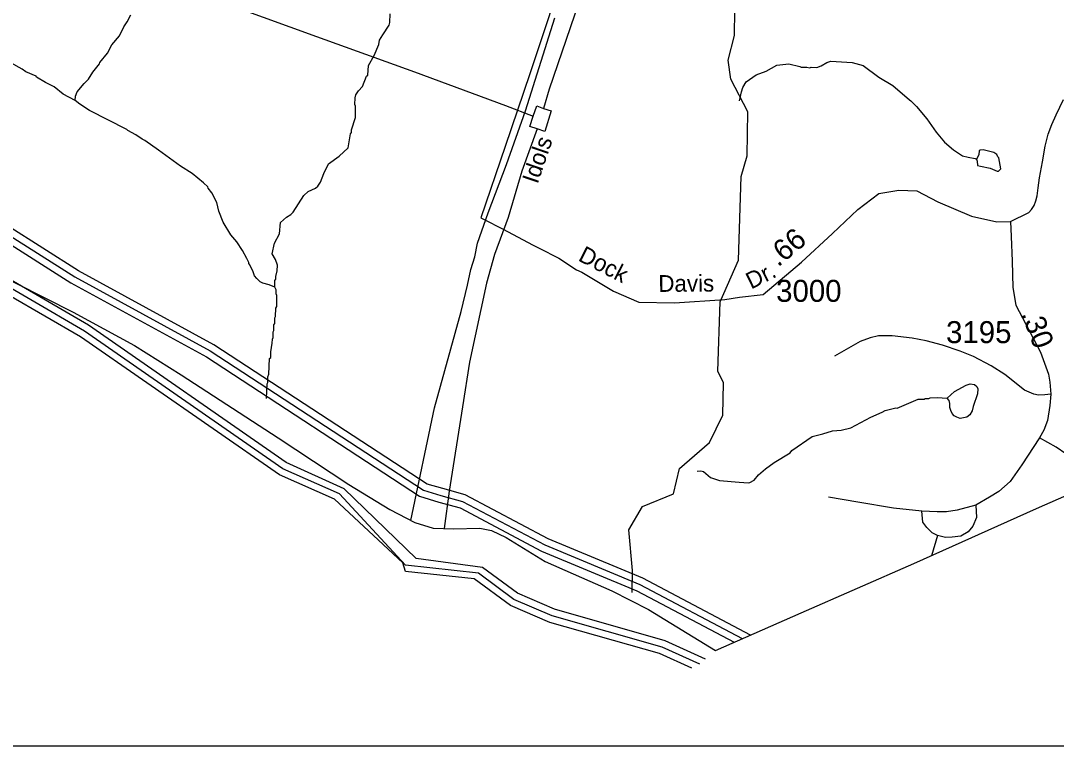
# Model space of a CAD drawing. Extents: x 1547597 to 1699558, y 810033 to 920809.
# Drawn here: x 1583488 to 1589376, y 811336 to 815460 of the extents above; entities that cross this region are included whole.
import ezdxf

# ---------------------------------------------------------------- set-up
doc = ezdxf.new("R2010")
doc.units = 0
for name, color, linetype in [('Exist Boundary Political CountyLine', 7, 'Continuous'), ('Exist Hydrographic Bay Label', 7, 'Continuous'), ('Exist Hydrographic Buffer Line', 7, 'Continuous'), ('Exist Hydrographic Creek Single Shore', 7, 'Continuous'), ('Exist Hydrographic Misc Water Feature', 7, 'Continuous'), ('Exist Railroad Mainline', 7, 'Continuous'), ('Exist Road Non-System Type 51', 7, 'Continuous'), ('Exist Road Secondary Mileage Hundredths English Label', 7, 'Continuous'), ('Exist Road Secondary Type 51 Attributed', 7, 'Continuous'), ('Exist Road Secondary Type 51 Label', 7, 'Continuous'), ('Exist Road Secondary Type 51 Number Label', 7, 'Continuous'), ('Exist Utilities Electrical Transmission Line', 7, 'Continuous'), ('Map Preparation Inset Cut Line', 7, 'Continuous')]:
    doc.layers.add(name, color=color, linetype=linetype)

msp = doc.modelspace()

# ---------------------------------------------------------------- linework, layer by layer
at = {"layer": 'Exist Boundary Political CountyLine'}
for points in [[(1587438.5, 811881.3), (1587925.9, 812095.3), (1588566.5, 812374.7), (1589263.6, 812687.4), (1590109.5, 813059.7), (1590806.5, 813364.4), (1591554.1, 813702), (1592251, 814008.7), (1592815, 814257.6), (1593254.5, 814449.6), (1606492.6, 820282.1), (1613860.9, 820194.5)], [(1582693, 814449.4), (1582927, 814290.4), (1583293.4, 814051.9), (1583785.6, 813804.5), (1584134.3, 813614.6), (1584399.2, 813446.8), (1584951, 813089), (1585352.7, 812824), (1585586.7, 812682.7), (1585728, 812607.6), (1585833.9, 812576.6), (1585948.7, 812572.2), (1586098.8, 812576.6), (1586165, 812563.4), (1586248.9, 812523.6), (1586469.6, 812386.7), (1586628.5, 812316.1), (1586849.3, 812218.9), (1587056.7, 812112.9), (1587438.5, 811881.3)]]:
    msp.add_lwpolyline(points, dxfattribs=at)
at = {"layer": 'Exist Hydrographic Bay Label'}
for points in [[(1585887.5, 812801.1), (1585799.5, 812825.6), (1584585.5, 813618.3), (1583816.6, 814037.7), (1583411.6, 814295.3)], [(1585675.6, 812329.1), (1585659.6, 812378.7), (1585272.5, 812741.1), (1584958.6, 812878.7), (1583827.5, 813663.2), (1583218.3, 814016.5)], [(1587025.5, 812291.9), (1586486.5, 812516.2), (1586015.5, 812765.4), (1585887.5, 812801.1)], [(1587303.7, 811781), (1587119.5, 811863.3), (1586496.6, 812040), (1586272.6, 812136.5), (1586066.6, 812288.4), (1585675.6, 812329.1)], [(1587637.3, 811968.6), (1587025.5, 812291.9)]]:
    msp.add_lwpolyline(points, dxfattribs=at)
at = {"layer": 'Exist Hydrographic Buffer Line'}
for points in [[(1580221, 816736.6), (1580592.6, 816438.9), (1580691.4, 816397.3), (1581643.3, 815550.5), (1581692.2, 815501.9), (1582490, 814782), (1582825.6, 814531), (1583370.6, 814226.6), (1583773.6, 813970.1), (1584544.4, 813549.6), (1585755.7, 812758.6), (1585866, 812724), (1585985.7, 812690.6), (1586449.1, 812445.5), (1586991.4, 812219.5), (1587543.8, 811927.6)], [(1587381.2, 811831), (1587152.2, 811936.4), (1586523.4, 812115.6), (1586312.6, 812206.3), (1586114.1, 812352.7), (1585735.6, 812403.3), (1585327.2, 812799.4), (1584997.9, 812948.9), (1583873.1, 813728.9), (1583258.4, 814085.7), (1582404.2, 814581.3), (1581630.1, 815328.9), (1580015.6, 816688.4)], [(1587349.1, 811803.1), (1587135.8, 811899.8), (1586510, 812077.8), (1586292.6, 812171.4), (1586090.4, 812320.5), (1585676, 812366.5), (1585299.9, 812770.3), (1584978.2, 812913.8), (1583850.3, 813696), (1583238.4, 814051.1), (1582379.9, 814549.1), (1581602.3, 815300.1), (1579988.1, 816659.3)], [(1583391.1, 814261), (1583795.1, 814003.9)], [(1583795.1, 814003.9), (1584565, 813583.9), (1585777.7, 812792.1), (1585876.7, 812762.5), (1586000.7, 812728), (1586467.9, 812480.8), (1587008.5, 812255.7), (1587590.6, 811948.1)]]:
    msp.add_lwpolyline(points, dxfattribs=at)
at = {"layer": 'Exist Hydrographic Creek Single Shore'}
msp.add_lwpolyline([(1586965.2, 812210.9), (1586967.3, 812335.5), (1586945.5, 812566), (1587022.5, 812699), (1587199.6, 812770.9), (1587234.6, 812914.7), (1587403.5, 813062.3), (1587480.5, 813218.3), (1587483.6, 813402), (1587451.5, 813468.3), (1587465.6, 813862), (1587568.6, 814099.5), (1587583.6, 814575.1), (1587618.5, 814692.6), (1587622.5, 814942), (1587525.5, 815127.9), (1587510.6, 815236.5), (1587545.5, 815376.9), (1587551.6, 815810.1), (1587784.5, 816330.6)], dxfattribs=at)
at = {"layer": 'Exist Hydrographic Misc Water Feature'}
for points in [[(1583797.9, 815006.4), (1583800.2, 815031.7), (1583808.6, 815056.2), (1583849.3, 815102.9), (1583873.6, 815127.1), (1583898.2, 815166.8), (1583934.8, 815214.5), (1583937, 815221.8), (1583981.8, 815275.1), (1584006.5, 815323), (1584049.3, 815374.6), (1584074.1, 815425.9), (1584092.6, 815454.2), (1584113.1, 815494)], [(1584932.9, 813945.2), (1584933.4, 813983), (1584937.7, 813991.1), (1584937.8, 814006.7), (1584946.2, 814038.5), (1584948.7, 814070.5), (1584937.3, 814102.7), (1584917.6, 814135.1), (1584930.5, 814195.6), (1584959.3, 814249.2), (1584964.3, 814313.1), (1584998.8, 814344.4), (1585022.9, 814357.8), (1585037.1, 814371.5), (1585098.5, 814467.1), (1585122.9, 814488.8), (1585163.1, 814507.6), (1585177.4, 814519.7), (1585191.7, 814543.2), (1585210.4, 814591.2), (1585237.2, 814647.3), (1585297.9, 814690.4), (1585350.6, 814737.7), (1585363.7, 814817.1), (1585367.8, 814825.2), (1585368.1, 814840.8), (1585391, 814910.9), (1585392.2, 814974.9), (1585388.2, 814983.2), (1585388.8, 815022.6), (1585393, 815038.9), (1585409.3, 815062.3), (1585431.7, 815086.5), (1585454.4, 815144.3), (1585460.6, 815150), (1585465.4, 815205.6), (1585498.3, 815261.6), (1585523.2, 815325.1), (1585527.5, 815348.8), (1585546.1, 815380.4), (1585582.8, 815434.7), (1585587.1, 815450.2), (1585587.8, 815498.6)], [(1583797.9, 815006.4), (1583728.3, 815043.1), (1583678.8, 815083.5), (1583629.2, 815108.2), (1583577.8, 815138.8), (1583575.8, 815145.4), (1583516, 815170.5), (1583496.2, 815184.8), (1583385, 815247.8), (1583307.9, 815299.4), (1583246.4, 815330.2), (1583196.9, 815366.5), (1583137.1, 815384.1), (1583129.1, 815383.5), (1583078.6, 815362.3), (1583068.7, 815360.9), (1582992.7, 815364), (1582976.8, 815367.7), (1582944.8, 815368.3), (1582890.8, 815380.9)], [(1587575.5, 815005.3), (1587586.1, 815056.8), (1587594.4, 815081.3), (1587612.9, 815112.9), (1587669.5, 815152), (1587726, 815173), (1587786.4, 815207.9), (1587854.6, 815215.5), (1587918.3, 815200.3), (1587926.2, 815196), (1587958.2, 815195.4), (1587974.4, 815191.8), (1587982.3, 815195.7), (1588014.5, 815195.1), (1588038.4, 815202.8), (1588070.8, 815221.8), (1588095, 815229.5), (1588214.8, 815222.2), (1588278.7, 815205.3), (1588367.6, 815139.5), (1588447.1, 815092.7), (1588541.9, 815009.6), (1588549.8, 815005.3), (1588581.3, 814972.7), (1588640.4, 814903.4), (1588693.2, 814826.8), (1588740.5, 814770), (1588791.9, 814725.5), (1588843.4, 814692.4), (1588875.2, 814684.4), (1588915.3, 814677.9), (1588923.2, 814673.6)], [(1584932.9, 813945.2), (1584901.2, 813959.8), (1584865.2, 813967.9), (1584849.4, 813976.5), (1584829.6, 813994.9), (1584817.8, 814010.8), (1584810.1, 814033.1), (1584790.8, 814072.9), (1584784.8, 814079.5), (1584784.9, 814085.3), (1584773.3, 814109.3), (1584747.9, 814154.2), (1584716.5, 814204), (1584683, 814242.4), (1584638.2, 814315.6), (1584615, 814377.6), (1584603.6, 814426.3), (1584574.6, 814482.7), (1584552.8, 814508.5), (1584551.1, 814515.1), (1584527.4, 814539.4), (1584462.2, 814592.4), (1584396.7, 814633.1), (1584272.1, 814725.1), (1584192.7, 814780), (1584178.7, 814786.1), (1584143.1, 814810.6), (1584097.4, 814835.4), (1584091.6, 814842), (1583879, 814950.5), (1583823.5, 814985.3), (1583797.9, 815006.4)], [(1588923.2, 814673.6), (1588927.1, 814661.2), (1588928.6, 814637.4), (1588944.5, 814633), (1589000.6, 814622.8), (1589040.1, 814605.6), (1589048.1, 814605.4), (1589060.3, 814617.5), (1589049.3, 814680.1), (1589043.4, 814685.9), (1589037.6, 814700), (1589021.8, 814711.8), (1588960, 814725.4), (1588944, 814724.9), (1588937.9, 814721.7), (1588935.6, 814697.1), (1588923.2, 814673.6)], [(1584885.8, 813313.5), (1584888.9, 813395.5), (1584893, 813403.6), (1584893.6, 813435.6), (1584897.8, 813451.1), (1584903.1, 813539.6), (1584909.2, 813546.9), (1584909.7, 813578.9), (1584918.2, 813627.1), (1584918.7, 813650.9), (1584922.7, 813659), (1584923.2, 813691.1), (1584927.4, 813699.2), (1584927.9, 813731.1), (1584931.9, 813739.3), (1584932.4, 813771.3), (1584936.4, 813778.6), (1584939.3, 813827), (1584943.3, 813835.1), (1584944.2, 813899), (1584940.3, 813907.3), (1584940.7, 813931.1), (1584932.9, 813945.2)], [(1588755.3, 813315.6), (1588798, 813352.4), (1588864.5, 813389.6), (1588886.7, 813395.8), (1588910.6, 813392.8), (1588924.5, 813381), (1588930.1, 813367), (1588927.8, 813339.1), (1588902.7, 813267.4), (1588898.6, 813242.9), (1588884.1, 813219.4), (1588867.8, 813207.4), (1588829.8, 813200), (1588809.8, 813206.9), (1588796, 813214.6), (1588784.1, 813227.1), (1588776.5, 813245.3), (1588770.7, 813261.1), (1588770.9, 813284.9), (1588767.1, 813301.4), (1588755.3, 813315.6)], [(1587334.8, 812899.5), (1587354.7, 812901.6), (1587370.9, 812897.2), (1587410.2, 812864.3), (1587462, 812847.7), (1587572, 812836.5), (1587626, 812833.7), (1587633.9, 812835.2), (1587658.2, 812849.5), (1587682.5, 812878.5), (1587723.3, 812913.8), (1587771.6, 812949.7), (1587862.5, 813004.5), (1587872.7, 813018.3), (1587987.9, 813096.4), (1588048.1, 813111.6), (1588104.5, 813128.5), (1588152.6, 813132.4), (1588208.7, 813146.9), (1588321.7, 813207.8), (1588386, 813234.4), (1588402.2, 813244.7), (1588464.6, 813259.9), (1588470.4, 813257.3), (1588591.3, 813309.8), (1588627.2, 813309.1), (1588631.4, 813313.1), (1588651.3, 813312.7), (1588659.4, 813316.6), (1588699.4, 813318.3), (1588755.3, 813315.6)]]:
    msp.add_lwpolyline(points, dxfattribs=at)
at = {"layer": 'Exist Railroad Mainline'}
msp.add_lwpolyline([(1585705.1, 812619.7), (1585841, 813259.6), (1585992.5, 813807), (1586027.9, 813956.7), (1586046.8, 814046.6), (1586069.4, 814118.4), (1586084.8, 814196), (1586146.5, 814367.5), (1586250.5, 814642.4), (1586357.6, 814947.4), (1586525.6, 815477.3)], dxfattribs=at)
at = {"layer": 'Exist Road Non-System Type 51'}
msp.add_line((1588699.8, 812534.1), (1588666.2, 812419.5), dxfattribs=at)
for points in [[(1589345.8, 813337.8), (1589310.7, 813333.5), (1589274.9, 813332.1), (1589249.2, 813337.8), (1589196.2, 813360.7), (1589083.1, 813449.4), (1589005.8, 813499.5), (1588906.3, 813552.5), (1588829, 813582.6), (1588728.8, 813616.9), (1588635.8, 813639.8), (1588557.1, 813655.6), (1588442.6, 813669.9), (1588365.3, 813668.5), (1588318, 813658.4), (1588260.8, 813637), (1588115.5, 813553.9)], [(1589281.4, 813090.2), (1589180.8, 812935.5), (1589113.3, 812841), (1589048.5, 812784.3), (1588997.2, 812751.9), (1588918.8, 812707.3)], [(1588612.4, 812672.9), (1588451.4, 812688.7), (1588248.1, 812724.4), (1588081.7, 812751.9)], [(1588918.8, 812707.3), (1588813.2, 812677.5), (1588751.1, 812669.4), (1588698.3, 812668.6), (1588612.4, 812672.9)], [(1588699.8, 812534.1), (1588671.1, 812549.8), (1588639.6, 812579.9), (1588618.2, 812609.9), (1588612.4, 812672.9)], [(1588918.8, 812707.3), (1588921.6, 812635.7), (1588901.6, 812587), (1588874.4, 812555.5), (1588832.9, 812531.2), (1588784.2, 812524), (1588747, 812522.6), (1588699.8, 812534.1)]]:
    msp.add_lwpolyline(points, dxfattribs=at)
at = {"layer": 'Exist Road Secondary Type 51 Attributed'}
for points in [[(1586736.3, 816351.8), (1586714.7, 816241.6), (1586703.6, 816183.3), (1586689.1, 816121.5), (1586639.8, 815947.5), (1586576.4, 815761.4), (1586491, 815481.6), (1586381.7, 815157.5), (1586243, 814745.8), (1586104.5, 814340.2), (1586122.4, 814330.7)], [(1589116, 814318.1), (1589219.5, 814370.9), (1589235.8, 814387.2), (1589249.8, 814409.9), (1589260.2, 814436.1), (1589267.2, 814464.1), (1589272.5, 814509.5), (1589281.2, 814567.2), (1589298.6, 814658), (1589313.1, 814747.8), (1589330.6, 814816), (1589351.6, 814870.1), (1589376, 814924.3), (1589416.2, 815011.7)], [(1586122.4, 814330.7), (1586226.9, 814278.2), (1586402.4, 814184.5), (1586436, 814168.3), (1586546.7, 814110.4), (1586647.6, 814045.1), (1586677.6, 814030.9), (1586858.7, 813923), (1587003, 813860.5), (1587205.8, 813856.6), (1587490.5, 813876.2), (1587575.4, 813889.7), (1587708.9, 813903.5), (1587927.3, 814086.9), (1588102.8, 814250.9), (1588247.1, 814387.5), (1588368, 814477.3), (1588481.1, 814496.8), (1588582.5, 814492.9), (1588703.4, 814430.4), (1588894.5, 814348.5), (1589038.8, 814317.2), (1589116, 814318.1)], [(1589116, 814318.1), (1589118.7, 814234.4), (1589126.1, 814093.9), (1589128.1, 813944.1), (1589145.7, 813842.8), (1589222, 813698.5), (1589286.4, 813576.8), (1589332.2, 813450.9), (1589339.4, 813405.1), (1589345.8, 813337.8), (1589338.6, 813273.4), (1589325.8, 813187.5), (1589305.7, 813133.1), (1589281.4, 813090.2)], [(1589572.3, 812823.3), (1589543.3, 812881.2), (1589497.5, 812937), (1589430.3, 812998.5), (1589375.9, 813037.2), (1589281.4, 813090.2)]]:
    msp.add_lwpolyline(points, dxfattribs=at)
at = {"layer": 'Exist Utilities Electrical Transmission Line'}
for points in [[(1579363, 819591), (1580225.9, 818652), (1580861.5, 817972), (1581222.2, 817572.1), (1581606, 817156.9), (1581926.3, 816807.4), (1582195.8, 816511.4), (1582350.7, 816340.6), (1582649.4, 816243.1), (1582831.4, 816176.6), (1583442.9, 815969.5), (1584198.5, 815710.5), (1584714.8, 815535.5), (1585169.3, 815371.2), (1585727.3, 815170), (1586244.5, 814977.5), (1586401.6, 814917.5)], [(1589955.3, 819241.7), (1589391.9, 818871.1), (1588908.8, 818538.1), (1588432, 818236.2), (1587850.4, 817847.7), (1587387.4, 817534.1), (1587310.4, 817465.2), (1587191.7, 817138.1), (1586963.4, 816466.1), (1586708.3, 815704.7), (1586492.5, 815070.3), (1586461.3, 814961.9)], [(1586401.6, 814917.5), (1586422.6, 814975.7), (1586461.3, 814961.9)], [(1586461.3, 814961.9), (1586504.1, 814948), (1586467.7, 814830.7), (1586423.7, 814845.2)], [(1586423.7, 814845.2), (1586382.2, 814858.6), (1586401.6, 814917.5)], [(1586423.7, 814845.2), (1586338, 814604.2), (1586259.4, 814341), (1586181.8, 814131.7), (1586135.6, 813967.8), (1586039.9, 813519), (1585999, 813266.5), (1585923.2, 812786.2), (1585896.4, 812574.2)]]:
    msp.add_lwpolyline(points, dxfattribs=at)
at = {"layer": 'Map Preparation Inset Cut Line'}
msp.add_lwpolyline([(1575502.6, 831307.2), (1641328.6, 831307.2), (1641328.6, 811336.3), (1575502.6, 811336.3)], close=True, dxfattribs=at)

# ---------------------------------------------------------------- texts
at = {"layer": 'Exist Road Secondary Mileage Hundredths English Label'}
for s, rotation, p in [('.66', 40.03043, (1587793.7, 814056.8)), ('.30', 290.53986, (1589175.8, 813794.8))]:
    msp.add_text(s, height=120, rotation=rotation, dxfattribs=at).set_placement(p)
at = {"layer": 'Exist Road Secondary Type 51 Label'}
for s, rotation, p in [('Idols', 71.14019, (1586426.5, 814528.2)), ('Dock', 332.75315, (1586652.3, 814099.2)), ('Davis', 0.33543, (1587113.5, 813918.9)), ('Dr.', 26.51249, (1587641, 813932.2))]:
    msp.add_text(s, height=95, rotation=rotation, dxfattribs=at).set_placement(p)
at = {"layer": 'Exist Road Secondary Type 51 Number Label'}
for s, p in [('3000', (1587783.2, 813862.3)), ('3195', (1588749.4, 813627.6))]:
    msp.add_text(s, height=125, dxfattribs=at).set_placement(p)

doc.saveas('drawing.dxf')
